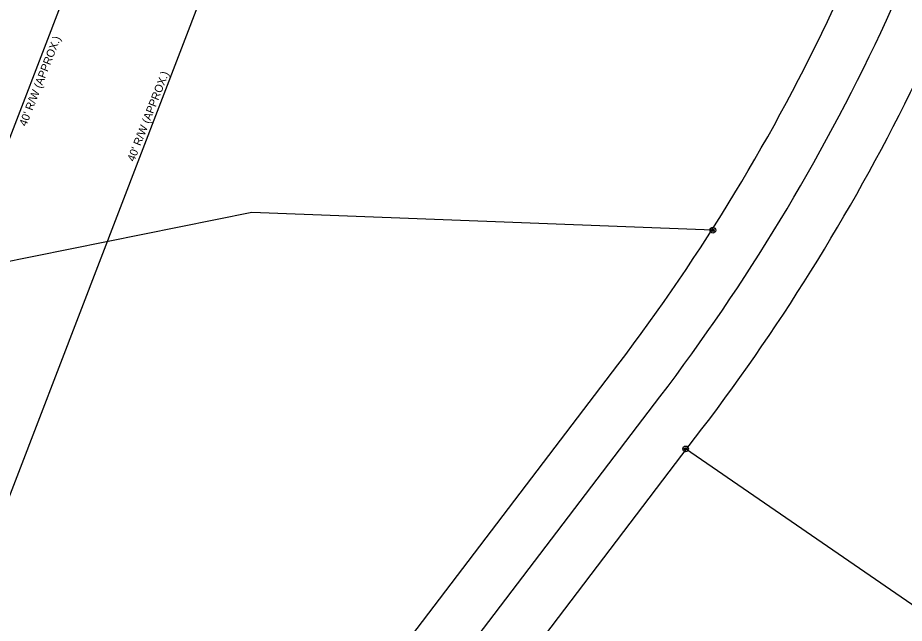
# Model space of a CAD drawing. Extents: x 1398271 to 1401121, y 1018936 to 1022764.
# Drawn here: x 1399852 to 1400405, y 1021227 to 1021605 of the extents above; entities that cross this region are included whole.
import ezdxf

# ---------------------------------------------------------------- set-up
doc = ezdxf.new("R2010")
doc.units = 0
for name, color, linetype in [('RD_EX_DV_Prop', 7, 'Continuous'), ('RD_EX_DV_Prop_txCode', 7, 'Continuous'), ('RD_EX_DV_PropPin', 7, 'Continuous'), ('RD_EX_Easement', 7, 'Continuous'), ('RD_EX_RW', 7, 'Continuous'), ('RD_HC_Cl', 7, 'Continuous'), ('RD_SMD_Locator', 7, 'Continuous')]:
    doc.layers.add(name, color=color, linetype=linetype)

msp = doc.modelspace()

# ---------------------------------------------------------------- linework, layer by layer
at = {"layer": 'RD_EX_DV_Prop'}
for p, q in [((1399997.75, 1021482.96), (1399102.95, 1021303.38)), ((1400285.68, 1021471.97), (1399997.75, 1021482.96)), ((1400285.83, 1021471.97), (1400285.68, 1021471.97)), ((1400416.63, 1021233.98), (1400268.65, 1021335.59))]:
    msp.add_line(p, q, dxfattribs=at)
at = {"layer": 'RD_EX_DV_PropPin'}
for p, q in [((1400284.95, 1021471.78), (1400284.95, 1021472.17)), ((1400284.98, 1021471.67), (1400284.98, 1021472.27)), ((1400285.02, 1021471.6), (1400285.02, 1021472.34)), ((1400285.05, 1021471.55), (1400285.05, 1021472.4)), ((1400285.09, 1021471.5), (1400285.09, 1021472.45)), ((1400285.12, 1021471.46), (1400285.12, 1021472.49)), ((1400285.16, 1021471.42), (1400285.16, 1021472.52)), ((1400285.19, 1021471.39), (1400285.19, 1021472.55)), ((1400285.23, 1021471.36), (1400285.23, 1021472.58)), ((1400285.26, 1021471.34), (1400285.26, 1021472.61)), ((1400285.3, 1021471.32), (1400285.3, 1021472.63)), ((1400285.33, 1021471.3), (1400285.33, 1021472.65)), ((1400285.37, 1021471.28), (1400285.37, 1021472.66)), ((1400285.4, 1021471.26), (1400285.4, 1021472.68)), ((1400285.44, 1021471.25), (1400285.44, 1021472.69)), ((1400285.47, 1021471.24), (1400285.47, 1021472.7)), ((1400285.51, 1021471.23), (1400285.51, 1021472.71)), ((1400285.54, 1021471.22), (1400285.54, 1021472.72)), ((1400285.58, 1021471.22), (1400285.58, 1021472.73)), ((1400285.61, 1021471.21), (1400285.61, 1021472.73)), ((1400285.65, 1021471.21), (1400285.65, 1021472.73)), ((1400285.68, 1021471.21), (1400285.68, 1021472.73)), ((1400285.72, 1021471.21), (1400285.72, 1021472.73)), ((1400285.75, 1021471.21), (1400285.75, 1021472.73)), ((1400285.79, 1021471.22), (1400285.79, 1021472.73)), ((1400285.82, 1021471.22), (1400285.82, 1021472.72)), ((1400285.86, 1021471.23), (1400285.86, 1021472.71)), ((1400285.89, 1021471.24), (1400285.89, 1021472.7)), ((1400285.93, 1021471.25), (1400285.93, 1021472.69)), ((1400285.96, 1021471.26), (1400285.96, 1021472.68)), ((1400286, 1021471.28), (1400286, 1021472.66)), ((1400286.03, 1021471.3), (1400286.03, 1021472.65)), ((1400286.07, 1021471.32), (1400286.07, 1021472.63)), ((1400286.1, 1021471.34), (1400286.1, 1021472.61)), ((1400286.14, 1021471.36), (1400286.14, 1021472.58)), ((1400286.17, 1021471.39), (1400286.17, 1021472.55)), ((1400286.21, 1021471.42), (1400286.21, 1021472.52)), ((1400286.24, 1021471.46), (1400286.24, 1021472.49)), ((1400286.28, 1021471.5), (1400286.28, 1021472.45)), ((1400286.31, 1021471.55), (1400286.31, 1021472.4)), ((1400286.35, 1021471.6), (1400286.35, 1021472.34)), ((1400286.38, 1021471.67), (1400286.38, 1021472.27)), ((1400286.42, 1021471.78), (1400286.42, 1021472.17)), ((1400267.92, 1021335.39), (1400267.92, 1021335.79)), ((1400267.95, 1021335.29), (1400267.95, 1021335.89)), ((1400267.99, 1021335.22), (1400267.99, 1021335.96)), ((1400268.02, 1021335.16), (1400268.02, 1021336.02)), ((1400268.06, 1021335.12), (1400268.06, 1021336.06)), ((1400268.09, 1021335.08), (1400268.09, 1021336.11)), ((1400268.13, 1021335.04), (1400268.13, 1021336.14)), ((1400268.16, 1021335.01), (1400268.16, 1021336.17)), ((1400268.2, 1021334.98), (1400268.2, 1021336.2)), ((1400268.23, 1021334.96), (1400268.23, 1021336.22)), ((1400268.27, 1021334.93), (1400268.27, 1021336.25)), ((1400268.3, 1021334.91), (1400268.3, 1021336.27)), ((1400268.34, 1021334.9), (1400268.34, 1021336.28)), ((1400268.37, 1021334.88), (1400268.37, 1021336.3)), ((1400268.41, 1021334.87), (1400268.41, 1021336.31)), ((1400268.44, 1021334.86), (1400268.44, 1021336.32)), ((1400268.48, 1021334.85), (1400268.48, 1021336.33)), ((1400268.51, 1021334.84), (1400268.51, 1021336.34)), ((1400268.55, 1021334.84), (1400268.55, 1021336.34)), ((1400268.58, 1021334.83), (1400268.58, 1021336.35)), ((1400268.62, 1021334.83), (1400268.62, 1021336.35)), ((1400268.65, 1021334.83), (1400268.65, 1021336.35)), ((1400268.69, 1021334.83), (1400268.69, 1021336.35)), ((1400268.72, 1021334.83), (1400268.72, 1021336.35)), ((1400268.76, 1021334.84), (1400268.76, 1021336.34)), ((1400268.79, 1021334.84), (1400268.79, 1021336.34)), ((1400268.83, 1021334.85), (1400268.83, 1021336.33)), ((1400268.86, 1021334.86), (1400268.86, 1021336.32)), ((1400268.9, 1021334.87), (1400268.9, 1021336.31)), ((1400268.93, 1021334.88), (1400268.93, 1021336.3)), ((1400268.97, 1021334.9), (1400268.97, 1021336.28)), ((1400269, 1021334.91), (1400269, 1021336.27)), ((1400269.04, 1021334.93), (1400269.04, 1021336.25)), ((1400269.07, 1021334.96), (1400269.07, 1021336.22)), ((1400269.11, 1021334.98), (1400269.11, 1021336.2)), ((1400269.14, 1021335.01), (1400269.14, 1021336.17)), ((1400269.18, 1021335.04), (1400269.18, 1021336.14)), ((1400269.21, 1021335.08), (1400269.21, 1021336.11)), ((1400269.25, 1021335.12), (1400269.25, 1021336.06)), ((1400269.28, 1021335.16), (1400269.28, 1021336.02)), ((1400269.32, 1021335.22), (1400269.32, 1021335.96)), ((1400269.35, 1021335.29), (1400269.35, 1021335.89)), ((1400269.39, 1021335.39), (1400269.39, 1021335.79))]:
    msp.add_line(p, q, dxfattribs=at)
for centre, radius in [((1400285.68, 1021471.97), 1.75), ((1400285.68, 1021471.97), 0.761), ((1400268.65, 1021335.59), 1.75), ((1400268.65, 1021335.59), 0.761)]:
    msp.add_circle(centre, radius, dxfattribs=at)
at = {"layer": 'RD_EX_Easement'}
for p, q in [((1399058.46, 1019485.02), (1400248.87, 1022572.6)), ((1399133.11, 1019456.25), (1400323.51, 1022543.82))]:
    msp.add_line(p, q, dxfattribs=at)
at = {"layer": 'RD_EX_RW'}
for p, q in [((1400050.04, 1021156.67), (1400226.39, 1021388.08)), ((1400102.47, 1021116.58), (1400278.89, 1021348.07))]:
    msp.add_line(p, q, dxfattribs=at)
for radius, end in [(1223.56, 346.98194), (1289.56, 334.03779)]:
    msp.add_arc((1399253.22, 1022129.72), radius, 322.68944, end, dxfattribs=at)
at = {"layer": 'RD_HC_Cl'}
msp.add_line((1399872.6, 1020869.39), (1400252.64, 1021368.08), dxfattribs=at)
msp.add_arc((1399253.22, 1022129.72), 1256.56, 322.68944, 346.98194, dxfattribs=at)
at = {"layer": 'RD_SMD_Locator'}
for centre in [(1400285.68, 1021471.97), (1400268.65, 1021335.59)]:
    msp.add_circle(centre, 0.15, dxfattribs=at)

# ---------------------------------------------------------------- texts
at = {"layer": 'RD_EX_DV_Prop_txCode'}
for p in [(1399856.96, 1021536.41), (1399924.45, 1021514.41)]:
    msp.add_text("40' R/W (APPROX.)", height=5, rotation=68.6308, dxfattribs=at).set_placement(p)

doc.saveas('drawing.dxf')
